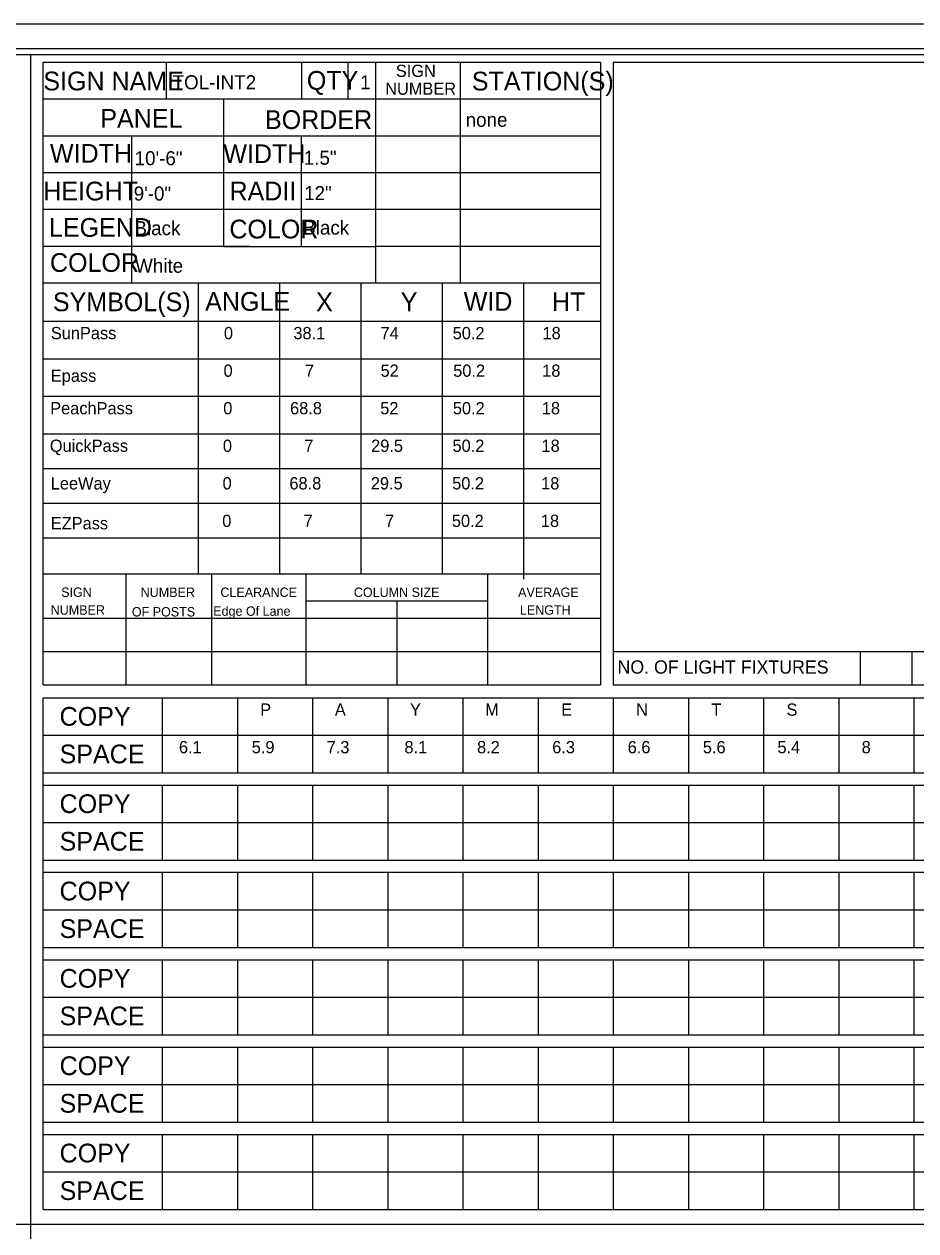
# Model space of a CAD drawing. Extents: x 17890628 to 17891459, y 17897314 to 17897992.
# Drawn here: x 17890765.84 to 17890794.41, y 17897458.18 to 17897496.82 of the extents above; entities that cross this region are included whole.
import ezdxf

# ---------------------------------------------------------------- set-up
doc = ezdxf.new("R2010")
doc.units = 0
for name, color, linetype in [('GSDims', 7, 'Continuous'), ('GSSign', 7, 'Continuous'), ('PlotBorder_dp', 7, 'Continuous'), ('SheetBorder_dp', 7, 'Continuous'), ('SheetLinesMisc2_dp', 7, 'Continuous'), ('TextMinor', 7, 'Continuous')]:
    doc.layers.add(name, color=color, linetype=linetype)

msp = doc.modelspace()

# ---------------------------------------------------------------- linework, layer by layer
at = {"layer": 'PlotBorder_dp'}
msp.add_lwpolyline([(17890701.346, 17897413.687), (17890830.745, 17897413.687), (17890830.745, 17897496.818), (17890701.346, 17897496.818)], close=True, dxfattribs=at)
at = {"layer": 'SheetBorder_dp'}
msp.add_line((17890705.659, 17897496.034), (17890826.432, 17897496.034), dxfattribs=at)
at = {"layer": 'SheetLinesMisc2_dp'}
for p, q in [((17890705.872, 17897495.849), (17890826.223, 17897495.849)), ((17890766.047, 17897495.849), (17890766.047, 17897420.931)), ((17890766.458, 17897475.661), (17890766.458, 17897495.599)), ((17890766.458, 17897495.599), (17890784.303, 17897495.599)), ((17890770.392, 17897495.599), (17890770.392, 17897494.422)), ((17890774.729, 17897495.599), (17890774.729, 17897494.422)), ((17890776.211, 17897495.599), (17890776.211, 17897494.422)), ((17890777.094, 17897495.599), (17890777.094, 17897488.533)), ((17890779.81, 17897495.599), (17890779.81, 17897488.533)), ((17890784.303, 17897495.599), (17890784.303, 17897475.661)), ((17890784.715, 17897495.599), (17890825.647, 17897495.599)), ((17890784.715, 17897495.599), (17890784.715, 17897475.661)), ((17890766.458, 17897494.422), (17890784.303, 17897494.422)), ((17890772.225, 17897494.422), (17890772.225, 17897489.698)), ((17890766.458, 17897493.244), (17890784.303, 17897493.244)), ((17890769.278, 17897493.244), (17890769.278, 17897488.533)), ((17890774.714, 17897493.231), (17890774.714, 17897489.698)), ((17890766.458, 17897492.066), (17890784.303, 17897492.066)), ((17890766.458, 17897490.888), (17890784.303, 17897490.888)), ((17890766.458, 17897489.711), (17890773.076, 17897489.711)), ((17890772.225, 17897489.698), (17890777.094, 17897489.698)), ((17890777.094, 17897489.711), (17890784.303, 17897489.711)), ((17890766.458, 17897488.533), (17890784.303, 17897488.533)), ((17890771.414, 17897488.51), (17890771.414, 17897479.217)), ((17890774.021, 17897488.51), (17890774.021, 17897479.217)), ((17890776.629, 17897488.51), (17890776.629, 17897479.217)), ((17890779.236, 17897488.51), (17890779.236, 17897479.217)), ((17890781.844, 17897488.51), (17890781.844, 17897479.044)), ((17890766.462, 17897487.307), (17890784.303, 17897487.307)), ((17890766.462, 17897486.105), (17890784.303, 17897486.105)), ((17890766.462, 17897484.902), (17890784.303, 17897484.902)), ((17890766.462, 17897483.7), (17890784.303, 17897483.7)), ((17890766.462, 17897482.59), (17890784.303, 17897482.59)), ((17890766.462, 17897481.48), (17890784.303, 17897481.48)), ((17890766.462, 17897480.37), (17890784.303, 17897480.37)), ((17890766.458, 17897479.217), (17890784.303, 17897479.217)), ((17890769.106, 17897479.217), (17890769.106, 17897475.661)), ((17890771.843, 17897479.217), (17890771.843, 17897475.661)), ((17890774.865, 17897479.217), (17890774.865, 17897475.661)), ((17890780.685, 17897479.217), (17890780.685, 17897475.661)), ((17890774.865, 17897478.355), (17890780.681, 17897478.355)), ((17890777.787, 17897478.355), (17890777.787, 17897475.661)), ((17890766.458, 17897477.798), (17890784.303, 17897477.798)), ((17890766.458, 17897476.729), (17890784.303, 17897476.729)), ((17890784.715, 17897476.729), (17890825.647, 17897476.729)), ((17890792.621, 17897476.729), (17890792.621, 17897475.661)), ((17890794.278, 17897476.729), (17890794.278, 17897475.661)), ((17890766.458, 17897475.661), (17890784.303, 17897475.661)), ((17890784.715, 17897475.661), (17890825.647, 17897475.661)), ((17890766.458, 17897458.862), (17890766.458, 17897475.25)), ((17890766.458, 17897475.25), (17890825.647, 17897475.25)), ((17890770.269, 17897475.25), (17890770.269, 17897472.846)), ((17890772.677, 17897475.25), (17890772.677, 17897472.846)), ((17890775.084, 17897475.25), (17890775.084, 17897472.846)), ((17890777.492, 17897475.25), (17890777.492, 17897472.846)), ((17890779.9, 17897475.25), (17890779.9, 17897472.846)), ((17890782.308, 17897475.25), (17890782.308, 17897472.846)), ((17890784.715, 17897475.25), (17890784.715, 17897472.846)), ((17890787.123, 17897475.25), (17890787.123, 17897472.846)), ((17890789.531, 17897475.25), (17890789.531, 17897472.846)), ((17890791.939, 17897475.25), (17890791.939, 17897472.846)), ((17890794.347, 17897475.25), (17890794.347, 17897472.846)), ((17890766.458, 17897474.048), (17890825.647, 17897474.048)), ((17890766.458, 17897472.846), (17890825.647, 17897472.846)), ((17890766.458, 17897472.453), (17890825.647, 17897472.453)), ((17890770.269, 17897472.453), (17890770.269, 17897470.049)), ((17890772.677, 17897472.453), (17890772.677, 17897470.049)), ((17890775.084, 17897472.453), (17890775.084, 17897470.049)), ((17890777.492, 17897472.453), (17890777.492, 17897470.049)), ((17890779.9, 17897472.453), (17890779.9, 17897470.049)), ((17890782.308, 17897472.453), (17890782.308, 17897470.049)), ((17890784.715, 17897472.453), (17890784.715, 17897470.049)), ((17890787.123, 17897472.453), (17890787.123, 17897470.049)), ((17890789.531, 17897472.453), (17890789.531, 17897470.049)), ((17890791.939, 17897472.453), (17890791.939, 17897470.049)), ((17890794.347, 17897472.453), (17890794.347, 17897470.049)), ((17890766.458, 17897471.251), (17890825.647, 17897471.251)), ((17890766.458, 17897470.049), (17890825.647, 17897470.049)), ((17890766.458, 17897469.657), (17890825.647, 17897469.657)), ((17890770.269, 17897469.657), (17890770.269, 17897467.252)), ((17890772.677, 17897469.657), (17890772.677, 17897467.252)), ((17890775.084, 17897469.657), (17890775.084, 17897467.252)), ((17890777.492, 17897469.657), (17890777.492, 17897467.252)), ((17890779.9, 17897469.657), (17890779.9, 17897467.252)), ((17890782.308, 17897469.657), (17890782.308, 17897467.252)), ((17890784.715, 17897469.657), (17890784.715, 17897467.252)), ((17890787.123, 17897469.657), (17890787.123, 17897467.252)), ((17890789.531, 17897469.657), (17890789.531, 17897467.252)), ((17890791.939, 17897469.657), (17890791.939, 17897467.252)), ((17890794.347, 17897469.657), (17890794.347, 17897467.252)), ((17890766.458, 17897468.454), (17890825.647, 17897468.454)), ((17890766.458, 17897467.252), (17890825.647, 17897467.252)), ((17890766.458, 17897466.86), (17890825.647, 17897466.86)), ((17890770.269, 17897466.86), (17890770.269, 17897464.455)), ((17890772.677, 17897466.86), (17890772.677, 17897464.455)), ((17890775.084, 17897466.86), (17890775.084, 17897464.455)), ((17890777.492, 17897466.86), (17890777.492, 17897464.455)), ((17890779.9, 17897466.86), (17890779.9, 17897464.455)), ((17890782.308, 17897466.86), (17890782.308, 17897464.455)), ((17890784.715, 17897466.86), (17890784.715, 17897464.455)), ((17890787.123, 17897466.86), (17890787.123, 17897464.455)), ((17890789.531, 17897466.86), (17890789.531, 17897464.455)), ((17890791.939, 17897466.86), (17890791.939, 17897464.455)), ((17890794.347, 17897466.86), (17890794.347, 17897464.455)), ((17890766.458, 17897465.658), (17890825.647, 17897465.658)), ((17890766.458, 17897464.455), (17890825.647, 17897464.455)), ((17890766.458, 17897464.063), (17890825.647, 17897464.063)), ((17890770.269, 17897464.063), (17890770.269, 17897461.659)), ((17890772.677, 17897464.063), (17890772.677, 17897461.659)), ((17890775.084, 17897464.063), (17890775.084, 17897461.659)), ((17890777.492, 17897464.063), (17890777.492, 17897461.659)), ((17890779.9, 17897464.063), (17890779.9, 17897461.659)), ((17890782.308, 17897464.063), (17890782.308, 17897461.659)), ((17890784.715, 17897464.063), (17890784.715, 17897461.659)), ((17890787.123, 17897464.063), (17890787.123, 17897461.659)), ((17890789.531, 17897464.063), (17890789.531, 17897461.659)), ((17890791.939, 17897464.063), (17890791.939, 17897461.659)), ((17890794.347, 17897464.063), (17890794.347, 17897461.659)), ((17890766.458, 17897462.861), (17890825.647, 17897462.861)), ((17890766.458, 17897461.659), (17890825.647, 17897461.659)), ((17890766.458, 17897461.267), (17890825.647, 17897461.267)), ((17890770.269, 17897461.267), (17890770.269, 17897458.862)), ((17890772.677, 17897461.267), (17890772.677, 17897458.862)), ((17890775.084, 17897461.267), (17890775.084, 17897458.862)), ((17890777.492, 17897461.267), (17890777.492, 17897458.862)), ((17890779.9, 17897461.267), (17890779.9, 17897458.862)), ((17890782.308, 17897461.267), (17890782.308, 17897458.862)), ((17890784.715, 17897461.267), (17890784.715, 17897458.862)), ((17890787.123, 17897461.267), (17890787.123, 17897458.862)), ((17890789.531, 17897461.267), (17890789.531, 17897458.862)), ((17890791.939, 17897461.267), (17890791.939, 17897458.862)), ((17890794.347, 17897461.267), (17890794.347, 17897458.862)), ((17890766.458, 17897460.065), (17890825.647, 17897460.065)), ((17890766.458, 17897458.862), (17890825.647, 17897458.862)), ((17890705.872, 17897458.39), (17890826.223, 17897458.39))]:
    msp.add_line(p, q, dxfattribs=at)

# ---------------------------------------------------------------- texts
at = {"layer": 'GSDims'}
for s, height, p in [('SunPass', 0.3921, (17890766.698, 17897486.729)), ('0', 0.392, (17890772.243, 17897486.729)), ('38.1', 0.3921, (17890774.468, 17897486.729)), ('74', 0.3921, (17890777.262, 17897486.729)), ('50.2', 0.3921, (17890779.571, 17897486.729)), ('18', 0.3921, (17890782.45, 17897486.729)), ('0', 0.392, (17890772.232, 17897485.526)), ('7', 0.392, (17890774.84, 17897485.526)), ('52', 0.3921, (17890777.261, 17897485.526)), ('50.2', 0.3921, (17890779.588, 17897485.526)), ('18', 0.3921, (17890782.439, 17897485.526)), ('Epass', 0.3921, (17890766.697, 17897485.364)), ('PeachPass', 0.3921, (17890766.677, 17897484.324)), ('0', 0.392, (17890772.222, 17897484.324)), ('68.8', 0.3921, (17890774.362, 17897484.324)), ('52', 0.3921, (17890777.25, 17897484.324)), ('50.2', 0.3921, (17890779.577, 17897484.324)), ('18', 0.3921, (17890782.428, 17897484.324)), ('QuickPass', 0.3921, (17890766.666, 17897483.121)), ('0', 0.392, (17890772.211, 17897483.121)), ('7', 0.392, (17890774.818, 17897483.121)), ('29.5', 0.3921, (17890776.959, 17897483.121)), ('50.2', 0.3921, (17890779.566, 17897483.121)), ('18', 0.3921, (17890782.417, 17897483.121)), ('LeeWay', 0.3921, (17890766.696, 17897481.916)), ('0', 0.392, (17890772.2, 17897481.919)), ('68.8', 0.3921, (17890774.341, 17897481.919)), ('29.5', 0.3921, (17890776.948, 17897481.919)), ('50.2', 0.3921, (17890779.555, 17897481.919)), ('18', 0.3921, (17890782.406, 17897481.919)), ('EZPass', 0.3921, (17890766.697, 17897480.64)), ('0', 0.392, (17890772.189, 17897480.716)), ('7', 0.392, (17890774.797, 17897480.716)), ('7', 0.392, (17890777.404, 17897480.716)), ('50.2', 0.3921, (17890779.545, 17897480.716)), ('18', 0.3921, (17890782.396, 17897480.716)), ('P', 0.392, (17890773.406, 17897474.672)), ('A', 0.392, (17890775.796, 17897474.672)), ('Y', 0.392, (17890778.204, 17897474.672)), ('M', 0.392, (17890780.612, 17897474.672)), ('E', 0.392, (17890783.048, 17897474.672)), ('N', 0.392, (17890785.447, 17897474.672)), ('T', 0.392, (17890787.856, 17897474.672)), ('S', 0.392, (17890790.264, 17897474.672)), ('6.1', 0.3921, (17890770.802, 17897473.47)), ('5.9', 0.3921, (17890773.135, 17897473.47)), ('7.3', 0.3921, (17890775.534, 17897473.47)), ('8.1', 0.3921, (17890778.026, 17897473.47)), ('8.2', 0.3921, (17890780.351, 17897473.47)), ('6.3', 0.3921, (17890782.759, 17897473.47)), ('6.6', 0.3921, (17890785.177, 17897473.47)), ('5.6', 0.3921, (17890787.585, 17897473.47)), ('5.4', 0.3921, (17890789.975, 17897473.47)), ('8', 0.392, (17890792.672, 17897473.47))]:
    msp.add_text(s, height=height, dxfattribs=at).set_placement(p)
at = {"layer": 'GSSign'}
for s, height, p in [('TOL-INT2', 0.4499, (17890770.6, 17897494.732)), ('1', 0.45, (17890776.606, 17897494.731)), ('none', 0.4499, (17890779.987, 17897493.531)), ('10\'-6"', 0.4499, (17890769.383, 17897492.3)), ('1.5"', 0.4499, (17890774.801, 17897492.316)), ('9\'-0"', 0.4499, (17890769.353, 17897491.169)), ('12"', 0.4499, (17890774.813, 17897491.182)), ('Black', 0.4499, (17890769.378, 17897490.06)), ('Black', 0.4499, (17890774.783, 17897490.077)), ('White', 0.4499, (17890769.398, 17897488.857))]:
    msp.add_text(s, height=height, dxfattribs=at).set_placement(p)
at = {"layer": 'TextMinor'}
for s, height, p in [('SIGN', 0.3921, (17890777.75, 17897495.127)), ('SIGN NAME', 0.5999, (17890766.458, 17897494.697)), ('QTY', 0.5999, (17890774.9, 17897494.717)), ('STATION(S)', 0.5999, (17890780.184, 17897494.694)), ('NUMBER', 0.3921, (17890777.409, 17897494.556)), ('PANEL', 0.5999, (17890768.283, 17897493.501)), ('BORDER', 0.5999, (17890773.559, 17897493.46)), ('WIDTH', 0.5999, (17890766.67, 17897492.38)), ('WIDTH', 0.5999, (17890772.225, 17897492.368)), ('HEIGHT', 0.5999, (17890766.458, 17897491.173)), ('RADII', 0.5999, (17890772.422, 17897491.175)), ('LEGEND', 0.5999, (17890766.639, 17897490.008)), ('COLOR', 0.5999, (17890772.418, 17897489.957)), ('COLOR', 0.5999, (17890766.67, 17897488.884)), ('SYMBOL(S)', 0.5999, (17890766.765, 17897487.625)), ('ANGLE', 0.5999, (17890771.643, 17897487.638)), ('X', 0.6, (17890775.195, 17897487.625)), ('Y', 0.6, (17890777.906, 17897487.625)), ('WID', 0.5999, (17890779.925, 17897487.638)), ('HT', 0.5999, (17890782.751, 17897487.627)), ('SIGN', 0.3, (17890767.03, 17897478.477)), ('NUMBER', 0.3, (17890769.577, 17897478.474)), ('CLEARANCE', 0.3, (17890772.131, 17897478.476)), ('COLUMN SIZE', 0.29998, (17890776.406, 17897478.476)), ('AVERAGE', 0.3, (17890781.668, 17897478.476)), ('NUMBER', 0.3, (17890766.694, 17897477.907)), ('OF POSTS', 0.3, (17890769.294, 17897477.85)), ('Edge Of Lane', 0.29998, (17890771.9, 17897477.872)), ('LENGTH', 0.3, (17890781.724, 17897477.907)), ('NO. OF LIGHT FIXTURES', 0.42516, (17890784.852, 17897476.019)), ('COPY', 0.6, (17890766.979, 17897474.351)), ('SPACE', 0.6, (17890766.979, 17897473.148)), ('COPY', 0.6, (17890766.979, 17897471.555)), ('SPACE', 0.6, (17890766.979, 17897470.352)), ('COPY', 0.6, (17890766.979, 17897468.758)), ('SPACE', 0.6, (17890766.979, 17897467.555)), ('COPY', 0.6, (17890766.979, 17897465.961)), ('SPACE', 0.6, (17890766.979, 17897464.759)), ('COPY', 0.6, (17890766.979, 17897463.164)), ('SPACE', 0.6, (17890766.979, 17897461.961)), ('COPY', 0.6, (17890766.979, 17897460.368)), ('SPACE', 0.6, (17890766.979, 17897459.165))]:
    msp.add_text(s, height=height, dxfattribs=at).set_placement(p)

doc.saveas('drawing.dxf')
